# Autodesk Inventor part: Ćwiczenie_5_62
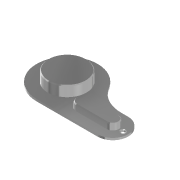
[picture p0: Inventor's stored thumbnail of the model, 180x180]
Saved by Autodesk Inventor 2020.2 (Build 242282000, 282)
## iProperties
Created: 2005-06
Part Number: Ćwiczenie_5_62
Document SubType Name: Modeling
Designer: F.Stasiak
Manufacturer: Standard
Standards Organization: Custom
Density: 1 g/cm^3
Material: Ogólny
Appearance: Chrom — polerowany
Manager: www.cadconsulting.pl
Company: Fabian Stasiak CAD Consulting
Author: F.Stasiak
Subject: Zbiór ćwiczeń. Autodesk Inventor 2020. Kurs podstawowy
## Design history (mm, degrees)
sketch "Szkic1"
  geometry: L1 (-75, -150)-(-75, 0); L2 (0, 0)-(0, -150); L3 (-75, -150)-(0, -150); L4 (0, -132.759)-(0, -150); L5 (0, -150)-(0, -132.759); A1 r 75 centre (0, 0) between (38.71, -64.238) and (-75, 0); A2 r 37.5 centre (-37.5, -150) between (-75, -150) and (0, -150); A3 r 80 centre (80, -132.759) between (38.71, -64.238) and (0, -132.759); 1 further point
  constraints: 10 end point, 7 tangent, 6 point on circle, 3 centre point, 2 coincident, 2 equal length, 1 horizontal, 1 perpendicular, 1 vertical
  dimensions: "d0" = 150 diameter of A1; "d1" = 150 vertical distance of A1.centre A2.centre; "d2" = 80 radius of A3
extrude "Wyciągnięcie proste1" new body sketch "Szkic1" distance "d3" = 10; taper "d4" = 0 deg
sketch "Szkic2"
  geometry: L1 (-75, -150)-(-75, 0) reference; L2 (0, -132.759)-(0, -150) reference; C1 r 47.5 at (0, 0); A1 r 37.5 centre (-37.5, -150) between (-75, -150) and (0, -150) reference; A2 r 80 centre (80, -132.759) between (38.71, -64.238) and (0, -132.759) reference; A3 r 75 centre (0, 0) between (38.71, -64.238) and (-75, 0) reference
  constraints: 1 centre point, 1 coincident
  dimensions: "d5" = 95 diameter of C1
extrude "Wyciągnięcie proste2" join sketch "Szkic2" distance "d6" = 25; taper "d7" = 0 deg
sketch "Szkic3"
  geometry: L1 (-75, -150)-(-75, 0) reference; L2 (0, -132.759)-(0, -150) reference; L3 (-52.5, -150)-(-52.5, -74.729); L4 (-22.5, -74.729)-(-22.5, -150); C1 r 47.5 at (0, 0) reference; A1 r 37.5 centre (-37.5, -150) between (-75, -150) and (0, -150) reference; A2 r 80 centre (80, -132.759) between (38.71, -64.238) and (0, -132.759) reference; A3 r 75 centre (0, 0) between (38.71, -64.238) and (-75, 0) reference; A4 r 15 centre (-37.5, -74.729) between (-22.5, -74.729) and (-52.5, -74.729); A5 r 15 centre (-37.5, -150) between (-52.5, -150) and (-22.5, -150)
  constraints: 4 end point, 4 point on circle, 4 tangent, 2 centre point, 2 parallel, 1 coincident
  dimensions: "d8" = 15 radius of A5
extrude "Wyciągnięcie proste3" join sketch "Szkic3" distance "d9" = 15; taper "d10" = 0 deg
feature "Skorupa1" dims "d11" = 5
chamfer "Faza1" distance "d12" = 2; stored, may be unused: second distance "d13" = 2, angle "d14" = 45 deg
sketch "Szkic4"
  geometry: A1 r 37.5 centre (-37.5, -150) between (-75, -150) and (0, -150) reference; 1 further point
  dimensions: "d15" = 25 distance of A1.centre point (-37.5, -175)
hole "Otwór1" sketch "Szkic4" at (-37.5, -175) diameter "d16" = 10; stored, may be unused: countersink angle "d20" = 120 deg, drill point angle "d22" = 118 deg; dims "d17" = 6, "d18" = 14, "d19" = 2, "d21" = 8
node "Bryła1"
node "Korpusy bryłowe"
node "Korpusy powierzchniowe"
node "Pętla rzutowana1"
node "Pętla rzutowana2"
